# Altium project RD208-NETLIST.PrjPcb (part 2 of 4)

## Sheet 4.SchDoc
size 420 x 297 mm
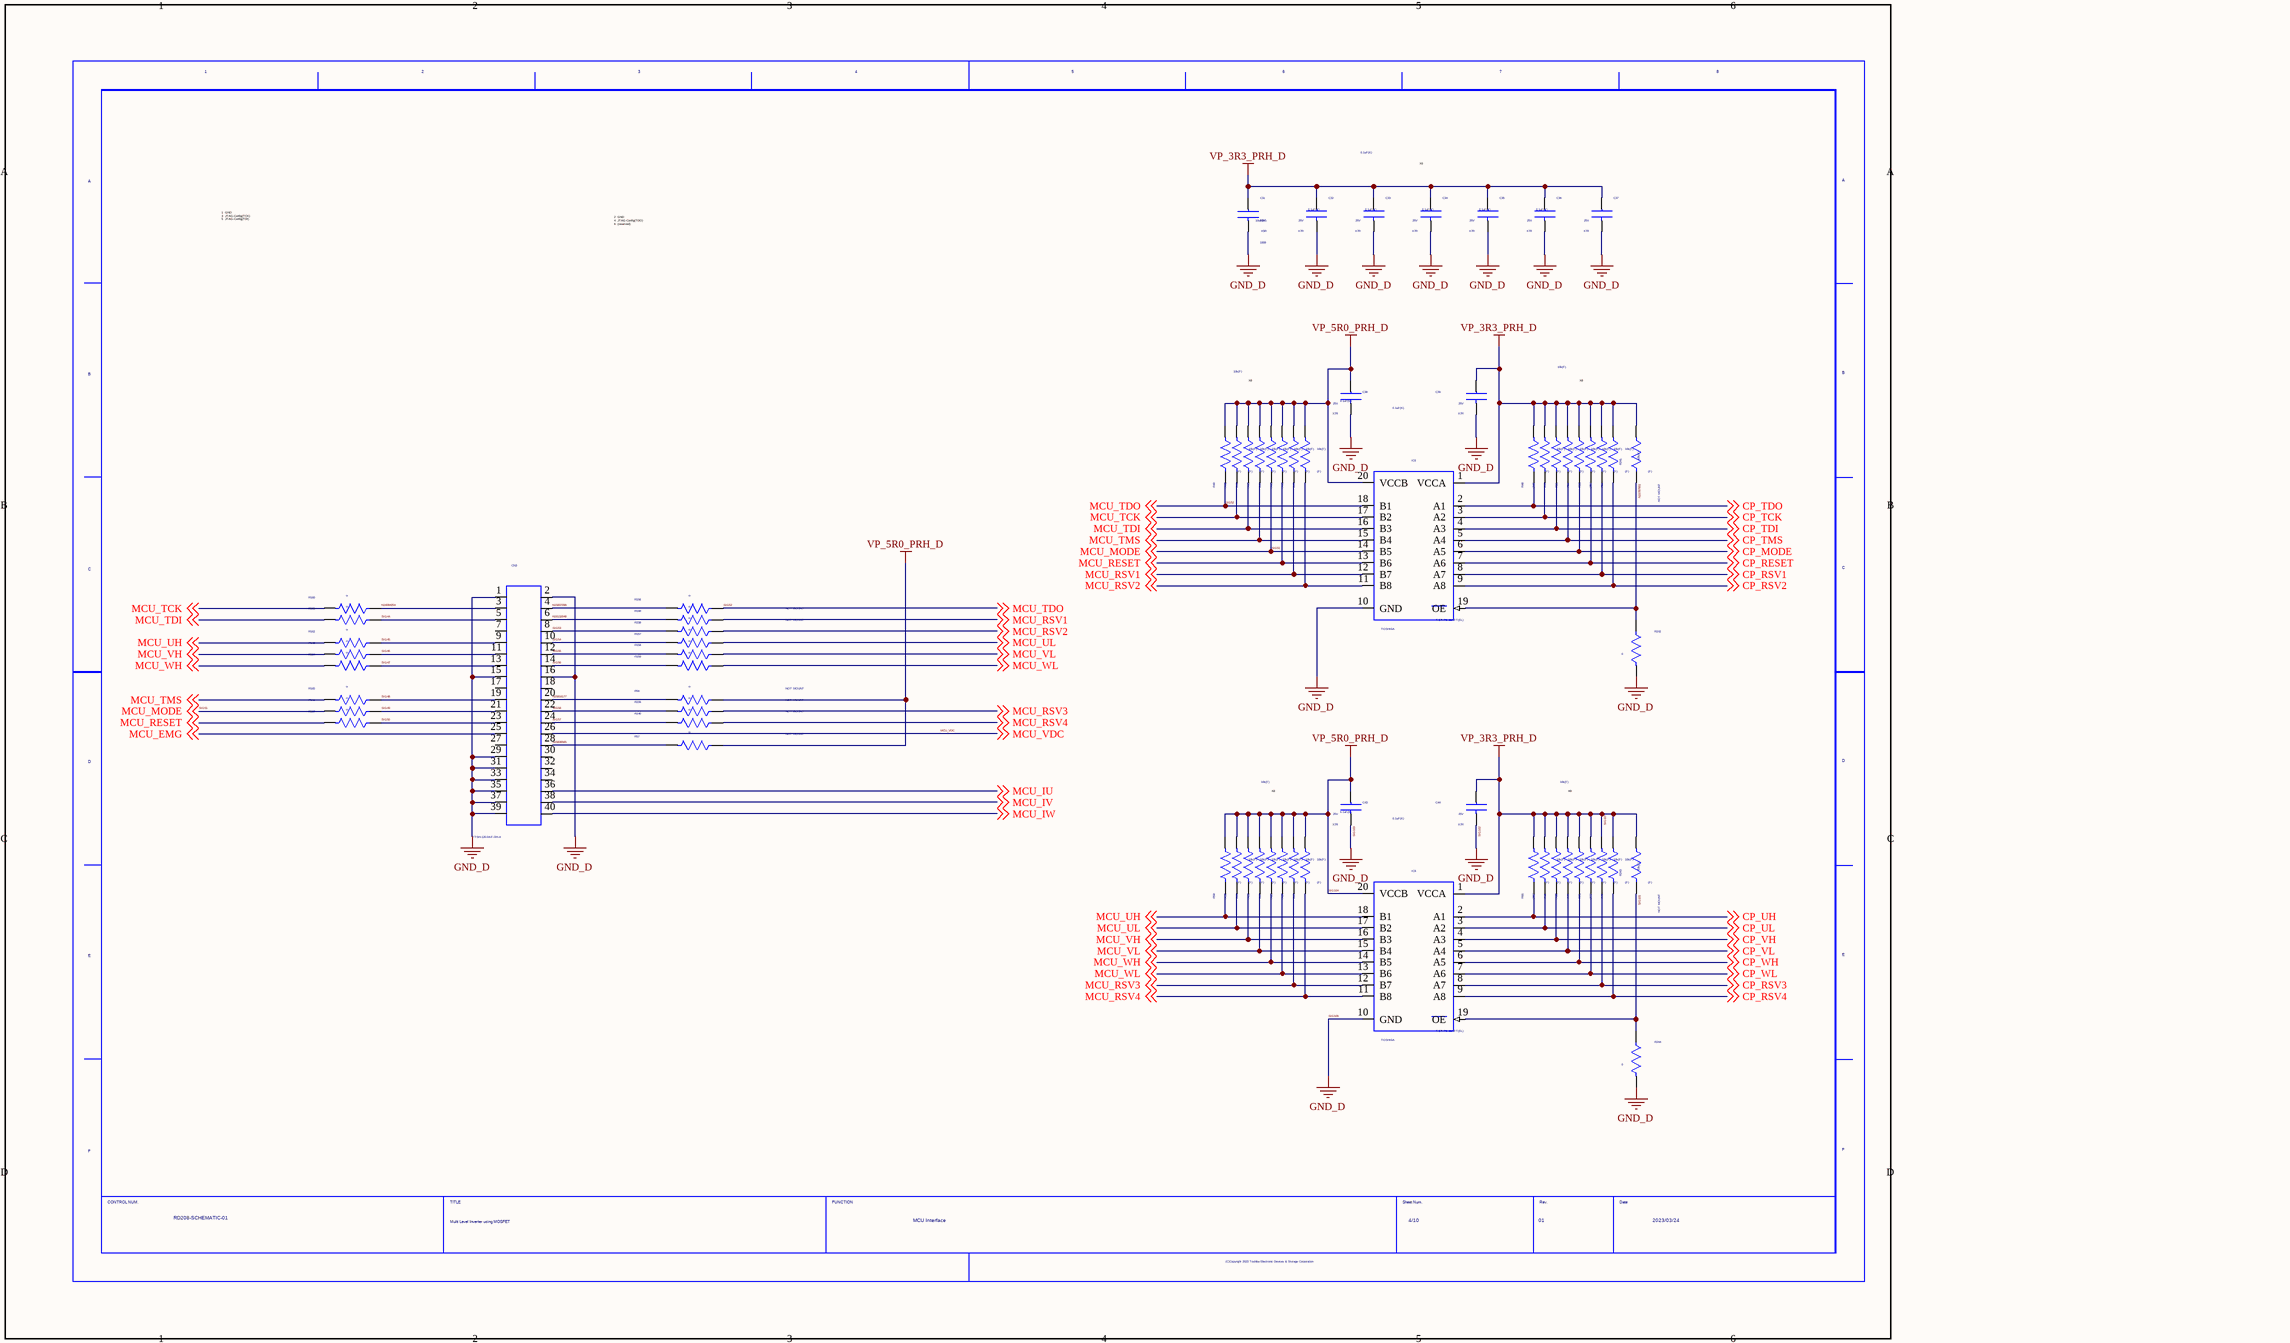
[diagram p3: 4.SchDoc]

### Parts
(Parts that share a designator on the sheet are numbered #1, #2 ... from top to bottom, then left to right.)
C31  VAL2: 10V  SIZECODESMD: 1608  VALUE4: X5R  VAL1: 10uF(M)  (hidden comment: GRM188R61A106ME69D)
C32  VAL2: 25V  VALUE4: X7R  VAL1: 0.1uF(K)  (hidden comment: GRM155R71E104KE14D)
C33  VAL2: 25V  VALUE4: X7R  VAL1: 0.1uF(K)  (hidden comment: GRM155R71E104KE14D)
C34  VAL2: 25V  VALUE4: X7R  VAL1: 0.1uF(K)  (hidden comment: GRM155R71E104KE14D)
C35  VAL2: 25V  VALUE4: X7R  VAL1: 0.1uF(K)  (hidden comment: GRM155R71E104KE14D)
C36  VAL2: 25V  VALUE4: X7R  VAL1: 0.1uF(K)  (hidden comment: GRM155R71E104KE14D)
C37  VAL2: 25V  VALUE4: X7R  VAL1: 0.1uF(K)  (hidden comment: GRM155R71E104KE14D)
C38  VAL2: 25V  VALUE4: X7R  VAL1: 0.1uF(K)  (hidden comment: GRM155R71E104KE14D)
C39  VAL2: 25V  VALUE4: X7R  VAL1: 0.1uF(K)  (hidden comment: GRM155R71E104KE14D)
C43  VAL2: 25V  VALUE4: X7R  VAL1: 0.1uF(K)  (hidden comment: GRM155R71E104KE14D)
C44  VAL2: 25V  VALUE4: X7R  VAL1: 0.1uF(K)  (hidden comment: GRM155R71E104KE14D)
CN3  VAL1: FTSH-120-04-F-DH-A  (hidden comment: FTSH_120_04_F_DH_A)
IC6  VAL1: TC7MPB9307FT(EL)  USERCOMPTEXT3: TOSHIBA  (hidden comment: TC7MPB9307FT)
IC8  VAL1: TC7MPB9307FT(EL)  USERCOMPTEXT3: TOSHIBA  (hidden comment: TC7MPB9307FT)
R40  VALUE4: (F)  VAL1: 10k(F)  (hidden comment: ERJ2RKF1002X)
R41  VALUE4: (F)  VAL1: 10k(F)  (hidden comment: ERJ2RKF1002X)
R42  VALUE4: (F)  VAL1: 10k(F)  (hidden comment: ERJ2RKF1002X)
R43  VALUE4: (F)  VAL1: 10k(F)  (hidden comment: ERJ2RKF1002X)
R44  VALUE4: (F)  VAL1: 10k(F)  (hidden comment: ERJ2RKF1002X)
R45  VALUE4: (F)  VAL1: 10k(F)  (hidden comment: ERJ2RKF1002X)
R46  VALUE4: (F)  VAL1: 10k(F)  (hidden comment: ERJ2RKF1002X)
R47  VALUE4: (F)  VAL1: 10k(F)  (hidden comment: ERJ2RKF1002X)
R48  VALUE4: (F)  VAL1: 10k(F)  (hidden comment: ERJ2RKF1002X)
R49  VALUE4: (F)  VAL1: 10k(F)  (hidden comment: ERJ2RKF1002X)
R50  VALUE4: (F)  VAL1: 10k(F)  (hidden comment: ERJ2RKF1002X)
R51  VALUE4: (F)  VAL1: 10k(F)  (hidden comment: ERJ2RKF1002X)
R52  VALUE4: (F)  VAL1: 10k(F)  (hidden comment: ERJ2RKF1002X)
R53  VALUE4: (F)  VAL1: 10k(F)  (hidden comment: ERJ2RKF1002X)
R54  VALUE4: (F)  VAL1: 10k(F)  (hidden comment: ERJ2RKF1002X)
R55  VALUE4: (F)  VAL1: 10k(F)  (hidden comment: ERJ2RKF1002X)
R56  VAL1: 0  NOTMOUNT: NOT MOUNT  (hidden comment: ERJ2GE0R00X)
R57  VAL1: 0  NOTMOUNT: NOT MOUNT  (hidden comment: ERJ2GE0R00X)
R58  VALUE4: (F)  VAL1: 10k(F)  (hidden comment: ERJ2RKF1002X)
R59  VALUE4: (F)  VAL1: 10k(F)  (hidden comment: ERJ2RKF1002X)
R60  VALUE4: (F)  VAL1: 10k(F)  (hidden comment: ERJ2RKF1002X)
R61  VALUE4: (F)  VAL1: 10k(F)  (hidden comment: ERJ2RKF1002X)
R62  VALUE4: (F)  VAL1: 10k(F)  (hidden comment: ERJ2RKF1002X)
R63  VALUE4: (F)  VAL1: 10k(F)  (hidden comment: ERJ2RKF1002X)
R64  VALUE4: (F)  VAL1: 10k(F)  (hidden comment: ERJ2RKF1002X)
R65  VALUE4: (F)  VAL1: 10k(F)  (hidden comment: ERJ2RKF1002X)
R66  VALUE4: (F)  VAL1: 10k(F)  (hidden comment: ERJ2RKF1002X)
R67  VALUE4: (F)  VAL1: 10k(F)  (hidden comment: ERJ2RKF1002X)
R68  VALUE4: (F)  VAL1: 10k(F)  (hidden comment: ERJ2RKF1002X)
R69  VALUE4: (F)  VAL1: 10k(F)  (hidden comment: ERJ2RKF1002X)
R70  VALUE4: (F)  VAL1: 10k(F)  (hidden comment: ERJ2RKF1002X)
R71  VALUE4: (F)  VAL1: 10k(F)  (hidden comment: ERJ2RKF1002X)
R72  VALUE4: (F)  VAL1: 10k(F)  (hidden comment: ERJ2RKF1002X)
R73  VALUE4: (F)  VAL1: 10k(F)  (hidden comment: ERJ2RKF1002X)
R156  VAL1: 0  (hidden comment: ERJ2GE0R00X)
R157  VAL1: 0  (hidden comment: ERJ2GE0R00X)
R158  VAL1: 0  (hidden comment: ERJ2GE0R00X)
R159  VAL1: 0  (hidden comment: ERJ2GE0R00X)
R160  VAL1: 0  (hidden comment: ERJ2GE0R00X)
R161  VAL1: 0  (hidden comment: ERJ2GE0R00X)
R162  VAL1: 0  (hidden comment: ERJ2GE0R00X)
R163  VAL1: 0  (hidden comment: ERJ2GE0R00X)
R164  VAL1: 0  (hidden comment: ERJ2GE0R00X)
R165  VAL1: 0  (hidden comment: ERJ2GE0R00X)
R166  VAL1: 0  (hidden comment: ERJ2GE0R00X)
R167  VAL1: 0  (hidden comment: ERJ2GE0R00X)
R198  VAL1: 0  NOTMOUNT: NOT MOUNT  (hidden comment: ERJ2GE0R00X)
R238  VAL1: 0  NOTMOUNT: NOT MOUNT  (hidden comment: ERJ2GE0R00X)
R239  VAL1: 0  NOTMOUNT: NOT MOUNT  (hidden comment: ERJ2GE0R00X)
R240  VAL1: 0  NOTMOUNT: NOT MOUNT  (hidden comment: ERJ2GE0R00X)
R241  VALUE4: (F)  VAL1: 10k(F)  NOTMOUNT: NOT MOUNT  (hidden comment: ERJ2RKF1002X)
R242  VAL1: 0  (hidden comment: ERJ2GE0R00X)
R243  VALUE4: (F)  VAL1: 10k(F)  NOTMOUNT: NOT MOUNT  (hidden comment: ERJ2RKF1002X)
R244  VAL1: 0  (hidden comment: ERJ2GE0R00X)
U?#4  DATE: 2023/03/24  TITLE: Multi Level Inverter using MOSFET  REVISION: 01  SHEETNUMBER: 4/10  DRAWINGNUMBER: RD208-SCHEMATIC-01  FUNCTION: MCU Interface  (hidden comment: WAKU_DEF100)

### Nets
GND_D: C31.2 C32.2 C33.2 C34.2 C35.2 C36.2 C37.2 C38.2 C39.2 C43.2 C44.2 CN3.1 CN3.2 CN3.15 CN3.16 CN3.29 CN3.31 CN3.33 CN3.35 CN3.37 CN3.39 IC6.10(GND) IC8.10(GND) R242.1 R244.1  [also labelled SIG102, SIG103, SIG106]  [project net SIG10]
SIG104: C38.1 C43.1 IC6.20(VCCB) IC8.20(VCCB) R40.1 R41.1 R42.1 R43.1 R44.1 R45.1 R46.1 R47.1 R56.2 R57.2 R58.1 R59.1 R60.1 R61.1 R62.1 R63.1 R64.1 R65.1  [also labelled VP_5R0_PRH_D]
SIG107: C31.1 C32.1 C33.1 C34.1 C35.1 C36.1 C37.1 C39.1 C44.1 IC6.1(VCCA) IC8.1(VCCA) R48.1 R49.1 R50.1 R51.1 R52.1 R53.1 R54.1 R55.1 R66.1 R67.1 R68.1 R69.1 R70.1 R71.1 R72.1 R73.1 R241.1 R243.1  [also labelled VP_3R3_PRH_D]
CP_MODE: IC6.6(A5) R52.2 ; off-sheet CP_MODE
CP_RESET: IC6.7(A6) R53.2 ; off-sheet CP_RESET
CP_RSV1: IC6.8(A7) R54.2 ; off-sheet CP_RSV1
CP_RSV2: IC6.9(A8) R55.2 ; off-sheet CP_RSV2
CP_RSV3: IC8.8(A7) R72.2 ; off-sheet CP_RSV3
CP_RSV4: IC8.9(A8) R73.2 ; off-sheet CP_RSV4
CP_TCK: IC6.3(A2) R49.2 ; off-sheet CP_TCK
CP_TDI: IC6.4(A3) R50.2 ; off-sheet CP_TDI
CP_TDO: IC6.2(A1) R48.2 ; off-sheet CP_TDO
CP_TMS: IC6.5(A4) R51.2 ; off-sheet CP_TMS
CP_UH: IC8.2(A1) R66.2 ; off-sheet CP_UH
CP_UL: IC8.3(A2) R67.2 ; off-sheet CP_UL
CP_VH: IC8.4(A3) R68.2 ; off-sheet CP_VH
CP_VL: IC8.5(A4) R69.2 ; off-sheet CP_VL
CP_WH: IC8.6(A5) R70.2 ; off-sheet CP_WH
CP_WL: IC8.7(A6) R71.2 ; off-sheet CP_WL
MCU_EMG: CN3.25 ; off-sheet MCU_EMG
MCU_IU: CN3.36 ; off-sheet MCU_IU
MCU_IV: CN3.38 ; off-sheet MCU_IV
MCU_IW: CN3.40 ; off-sheet MCU_IW
MCU_RESET: IC6.13(B6) R45.2 R167.1 ; off-sheet MCU_RESET
MCU_RSV1: IC6.12(B7) R46.2 R198.2 ; off-sheet MCU_RSV1
MCU_RSV2: IC6.11(B8) R47.2 R238.2 ; off-sheet MCU_RSV2
MCU_RSV3: IC8.12(B7) R64.2 R239.2 ; off-sheet MCU_RSV3
MCU_RSV4: IC8.11(B8) R65.2 R240.2 ; off-sheet MCU_RSV4
MCU_TCK: IC6.17(B2) R41.2 R160.1 ; off-sheet MCU_TCK
MCU_TDI: IC6.16(B3) R42.2 R161.1 ; off-sheet MCU_TDI
MCU_TMS: IC6.15(B4) R43.2 R165.1 ; off-sheet MCU_TMS
MCU_UH: IC8.18(B1) R58.2 R162.1 ; off-sheet MCU_UH
MCU_UL: IC8.17(B2) R59.2 R157.2 ; off-sheet MCU_UL
MCU_VDC: CN3.26 ; off-sheet MCU_VDC
MCU_VH: IC8.16(B3) R60.2 R163.1 ; off-sheet MCU_VH
MCU_VL: IC8.15(B4) R61.2 R158.2 ; off-sheet MCU_VL
MCU_WH: IC8.14(B5) R62.2 R164.1 ; off-sheet MCU_WH
MCU_WL: IC8.13(B6) R63.2 R159.2 ; off-sheet MCU_WL
N15787951: IC6.19(OE) R241.2 R242.2
N15816177: CN3.20 R56.1
N15836565: CN3.28 R57.1
N15837096: CN3.4 R156.1
N16084254: CN3.3 R160.2
N16132048: CN3.6 R198.1
SIG44: CN3.5 R161.2
SIG45: CN3.9 R162.2
SIG46: CN3.11 R163.2
SIG47: CN3.13 R164.2
SIG48: CN3.19 R165.2
SIG49: CN3.21 R166.2
SIG50: CN3.23 R167.2
SIG51: IC6.14(B5) R44.2 R166.1 ; off-sheet MCU_MODE  [also labelled MCU_MODE]
SIG52: IC6.18(B1) R40.2 R156.2 ; off-sheet MCU_TDO  [also labelled MCU_TDO]
SIG53: CN3.8 R238.1
SIG54: CN3.10 R157.1
SIG55: CN3.12 R158.1
SIG56: CN3.14 R159.1
SIG57: CN3.24 R240.1
SIG58: CN3.22 R239.1
SIG101: IC8.19(OE) R243.2 R244.2

Not connected (* = marked no-connect by the designer): CN3 7 17 18 27 30 32 34

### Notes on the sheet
- X6
- 1  GND
  3  JTAG-Config(TCK)
  5  JTAG-Config(TDI)
  7  (n.c.)
  9  High-side gate driver signal (U-Phase)
  11  High-side gate driver signal (V-Phase)
  13  High-side gate driver signal (W-Phase)
  15  GND
  17  (n.c.)
  19  JTAG-Config(TMS)
  21  CPLD-MODE
  23  CPLD-RESET
  25  EMG
  27  (n.c.)
  29  GND
  31  GND
  33  GND
  35  GND
  37  GND
  39  GND
- 2  GND
  4  JTAG-Config(TDO)
  6  (reserved)
  8  (reserved)
  10  Low-side gate driver signal (U-Phase)
  12  Low-side gate driver signal (V-Phase)
  14  Low-side gate driver signal (W-Phase)
  16  GND
  18  (n.c.)
  20  5V Input
  22  (reserved)
  24  (reserved)
  26  Inverter bus voltage divider voltage (Vdc)
  28  5V Input
  30  (n.c.)
  32  (n.c.)
  34  (n.c.)
  36  U-phase current value
  38  V-phase current value
  40  W-phase current value
- X8

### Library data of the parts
C31 = GRM188R61A106ME69D: MANUFACTURER: MURATA; ITEM: CAP Ceramic; TIME: 08:44:46; UPDATEUSER: t5459927; SAVECOUNT: 1; OriginalSymbolOrigin: (0,0); INSTANCENAME: INS15850047
C32 = GRM155R71E104KE14D: MANUFACTURER: MURATA; ITEM: CAP Ceramic; SIZECODESMD: 1005; TIME: 08:44:45; UPDATEUSER: t5459927; SAVECOUNT: 1; OriginalSymbolOrigin: (0,0); INSTANCENAME: INS15848437
C33 = GRM155R71E104KE14D: MANUFACTURER: MURATA; ITEM: CAP Ceramic; SIZECODESMD: 1005; TIME: 08:44:45; UPDATEUSER: t5459927; SAVECOUNT: 1; OriginalSymbolOrigin: (0,0); INSTANCENAME: INS15848594
C34 = GRM155R71E104KE14D: MANUFACTURER: MURATA; ITEM: CAP Ceramic; SIZECODESMD: 1005; TIME: 08:44:45; UPDATEUSER: t5459927; SAVECOUNT: 1; OriginalSymbolOrigin: (0,0); INSTANCENAME: INS15848750
C35 = GRM155R71E104KE14D: MANUFACTURER: MURATA; ITEM: CAP Ceramic; SIZECODESMD: 1005; TIME: 08:44:45; UPDATEUSER: t5459927; SAVECOUNT: 1; OriginalSymbolOrigin: (0,0); INSTANCENAME: INS15848907
C36 = GRM155R71E104KE14D: MANUFACTURER: MURATA; ITEM: CAP Ceramic; SIZECODESMD: 1005; TIME: 08:44:45; UPDATEUSER: t5459927; SAVECOUNT: 1; OriginalSymbolOrigin: (0,0); INSTANCENAME: INS15849085
C37 = GRM155R71E104KE14D: MANUFACTURER: MURATA; ITEM: CAP Ceramic; SIZECODESMD: 1005; TIME: 08:44:45; UPDATEUSER: t5459927; SAVECOUNT: 1; OriginalSymbolOrigin: (0,0); INSTANCENAME: INS15849105
C38 C43 = GRM155R71E104KE14D: MANUFACTURER: MURATA; ITEM: CAP Ceramic; SIZECODESMD: 1005; TIME: 08:44:45; UPDATEUSER: t5459927; SAVECOUNT: 1; OriginalSymbolOrigin: (0,0); INSTANCENAME: INS15846963
C39 C44 = GRM155R71E104KE14D: MANUFACTURER: MURATA; ITEM: CAP Ceramic; SIZECODESMD: 1005; TIME: 08:44:45; UPDATEUSER: t5459927; SAVECOUNT: 1; OriginalSymbolOrigin: (0,0); INSTANCENAME: INS15846983
CN3 = FTSH_120_04_F_DH_A: MANUFACTURER: Samtec; COMP: FTSH-120-04-F-DH-A-AEP; ITEM: Connector; TIME: 08:44:46; UPDATEUSER: t5459927; SAVECOUNT: 1; SAVEAREA0: -36272,-54408,42126,2984; OriginalSymbolOrigin: (0,0); INSTANCENAME: INS16810272
IC6 IC8 = TC7MPB9307FT: ITEM: IC BUS SW; VAL2: BUS SW; TIME: 08:44:46; UPDATEUSER: PS4_common_PC; UPDATETIME: 15:59:21; SAVECOUNT: 4; SAVEAREA0: -17429,-46731,34553,-8676; OriginalSymbolOrigin: (0,0)
R40 R58 = ERJ2RKF1002X: MANUFACTURER: Panasonic; ITEM: Register; VAL2: 100mW; SIZECODESMD: 1005; TIME: 08:44:45; UPDATEUSER: t5459927; SAVECOUNT: 1; OriginalSymbolOrigin: (0,0); INSTANCENAME: INS15795606
R41 R59 = ERJ2RKF1002X: MANUFACTURER: Panasonic; ITEM: Register; VAL2: 100mW; SIZECODESMD: 1005; TIME: 08:44:45; UPDATEUSER: t5459927; SAVECOUNT: 1; OriginalSymbolOrigin: (0,0); INSTANCENAME: INS17125057
R42 R60 = ERJ2RKF1002X: MANUFACTURER: Panasonic; ITEM: Register; VAL2: 100mW; SIZECODESMD: 1005; TIME: 08:44:45; UPDATEUSER: t5459927; SAVECOUNT: 1; OriginalSymbolOrigin: (0,0); INSTANCENAME: INS17125150
R43 R61 = ERJ2RKF1002X: MANUFACTURER: Panasonic; ITEM: Register; VAL2: 100mW; SIZECODESMD: 1005; TIME: 08:44:45; UPDATEUSER: t5459927; SAVECOUNT: 1; OriginalSymbolOrigin: (0,0); INSTANCENAME: INS17125244
R44 R62 = ERJ2RKF1002X: MANUFACTURER: Panasonic; ITEM: Register; VAL2: 100mW; SIZECODESMD: 1005; TIME: 08:44:45; UPDATEUSER: t5459927; SAVECOUNT: 1; OriginalSymbolOrigin: (0,0); INSTANCENAME: INS17125339
R45 R63 = ERJ2RKF1002X: MANUFACTURER: Panasonic; ITEM: Register; VAL2: 100mW; SIZECODESMD: 1005; TIME: 08:44:45; UPDATEUSER: t5459927; SAVECOUNT: 1; OriginalSymbolOrigin: (0,0); INSTANCENAME: INS17125433
R46 R64 = ERJ2RKF1002X: MANUFACTURER: Panasonic; ITEM: Register; VAL2: 100mW; SIZECODESMD: 1005; TIME: 08:44:45; UPDATEUSER: t5459927; SAVECOUNT: 1; OriginalSymbolOrigin: (0,0); INSTANCENAME: INS17125527
R47 R65 = ERJ2RKF1002X: MANUFACTURER: Panasonic; ITEM: Register; VAL2: 100mW; SIZECODESMD: 1005; TIME: 08:44:45; UPDATEUSER: t5459927; SAVECOUNT: 1; OriginalSymbolOrigin: (0,0); INSTANCENAME: INS17125624
R48 R66 = ERJ2RKF1002X: MANUFACTURER: Panasonic; ITEM: Register; VAL2: 100mW; SIZECODESMD: 1005; TIME: 08:44:45; UPDATEUSER: t5459927; SAVECOUNT: 1; OriginalSymbolOrigin: (0,0); INSTANCENAME: INS17126711
R49 R67 = ERJ2RKF1002X: MANUFACTURER: Panasonic; ITEM: Register; VAL2: 100mW; SIZECODESMD: 1005; TIME: 08:44:45; UPDATEUSER: t5459927; SAVECOUNT: 1; OriginalSymbolOrigin: (0,0); INSTANCENAME: INS17126722
R50 R68 = ERJ2RKF1002X: MANUFACTURER: Panasonic; ITEM: Register; VAL2: 100mW; SIZECODESMD: 1005; TIME: 08:44:45; UPDATEUSER: t5459927; SAVECOUNT: 1; OriginalSymbolOrigin: (0,0); INSTANCENAME: INS17126733
R51 R69 = ERJ2RKF1002X: MANUFACTURER: Panasonic; ITEM: Register; VAL2: 100mW; SIZECODESMD: 1005; TIME: 08:44:45; UPDATEUSER: t5459927; SAVECOUNT: 1; OriginalSymbolOrigin: (0,0); INSTANCENAME: INS17126744
R52 R70 = ERJ2RKF1002X: MANUFACTURER: Panasonic; ITEM: Register; VAL2: 100mW; SIZECODESMD: 1005; TIME: 08:44:45; UPDATEUSER: t5459927; SAVECOUNT: 1; OriginalSymbolOrigin: (0,0); INSTANCENAME: INS17126755
R53 R71 = ERJ2RKF1002X: MANUFACTURER: Panasonic; ITEM: Register; VAL2: 100mW; SIZECODESMD: 1005; TIME: 08:44:45; UPDATEUSER: t5459927; SAVECOUNT: 1; OriginalSymbolOrigin: (0,0); INSTANCENAME: INS17126766
R54 R72 = ERJ2RKF1002X: MANUFACTURER: Panasonic; ITEM: Register; VAL2: 100mW; SIZECODESMD: 1005; TIME: 08:44:45; UPDATEUSER: t5459927; SAVECOUNT: 1; OriginalSymbolOrigin: (0,0); INSTANCENAME: INS17126777
R55 R73 = ERJ2RKF1002X: MANUFACTURER: Panasonic; ITEM: Register; VAL2: 100mW; SIZECODESMD: 1005; TIME: 08:44:45; UPDATEUSER: t5459927; SAVECOUNT: 1; OriginalSymbolOrigin: (0,0); INSTANCENAME: INS17126788
R56 R57 = ERJ2GE0R00X: MANUFACTURER: Panasonic; ITEM: Register; VAL2: 1/10W; SIZECODESMD: 1005; TIME: 08:44:45; UPDATEUSER: t5459927; SAVECOUNT: 1; OriginalSymbolOrigin: (0,0); INSTANCENAME: INS17265222
R156-R159 = ERJ2GE0R00X: MANUFACTURER: Panasonic; ITEM: Register; VAL2: 1/10W; SIZECODESMD: 1005; TIME: 08:44:45; UPDATEUSER: t5459927; SAVECOUNT: 1; OriginalSymbolOrigin: (0,0); INSTANCENAME: INS16082588
R160-R167 = ERJ2GE0R00X: MANUFACTURER: Panasonic; ITEM: Register; VAL2: 1/10W; SIZECODESMD: 1005; TIME: 08:44:45; UPDATEUSER: t5459927; SAVECOUNT: 1; OriginalSymbolOrigin: (0,0); INSTANCENAME: INS16084230
R198 R238-R240 = ERJ2GE0R00X: MANUFACTURER: Panasonic; ITEM: Register; VAL2: 1/10W; SIZECODESMD: 1005; TIME: 08:44:45; UPDATEUSER: t5459927; SAVECOUNT: 1; OriginalSymbolOrigin: (0,0); INSTANCENAME: INS16693080
R241 R243 = ERJ2RKF1002X: MANUFACTURER: Panasonic; ITEM: Register; VAL2: 100mW; SIZECODESMD: 1005; TIME: 08:44:45; UPDATEUSER: t5459927; SAVECOUNT: 1; OriginalSymbolOrigin: (0,0); INSTANCENAME: INS16663974
R242 R244 = ERJ2GE0R00X: MANUFACTURER: Panasonic; ITEM: Register; VAL2: 1/10W; SIZECODESMD: 1005; TIME: 08:44:45; UPDATEUSER: t5459927; SAVECOUNT: 1; OriginalSymbolOrigin: (0,0); INSTANCENAME: INS16664582
U?#4 = WAKU_DEF100: PLOTTIME: HH:MM; SAVEAREA0: 185750,-43960,448537,75779; TIME: 14:30:25; UPDATEUSER: PS4_common_PC; UPDATETIME: 08:24:35; SAVECOUNT: 8; OriginalSymbolOrigin: (10160,284480)

## Sheet 5.SchDoc
size 420 x 297 mm
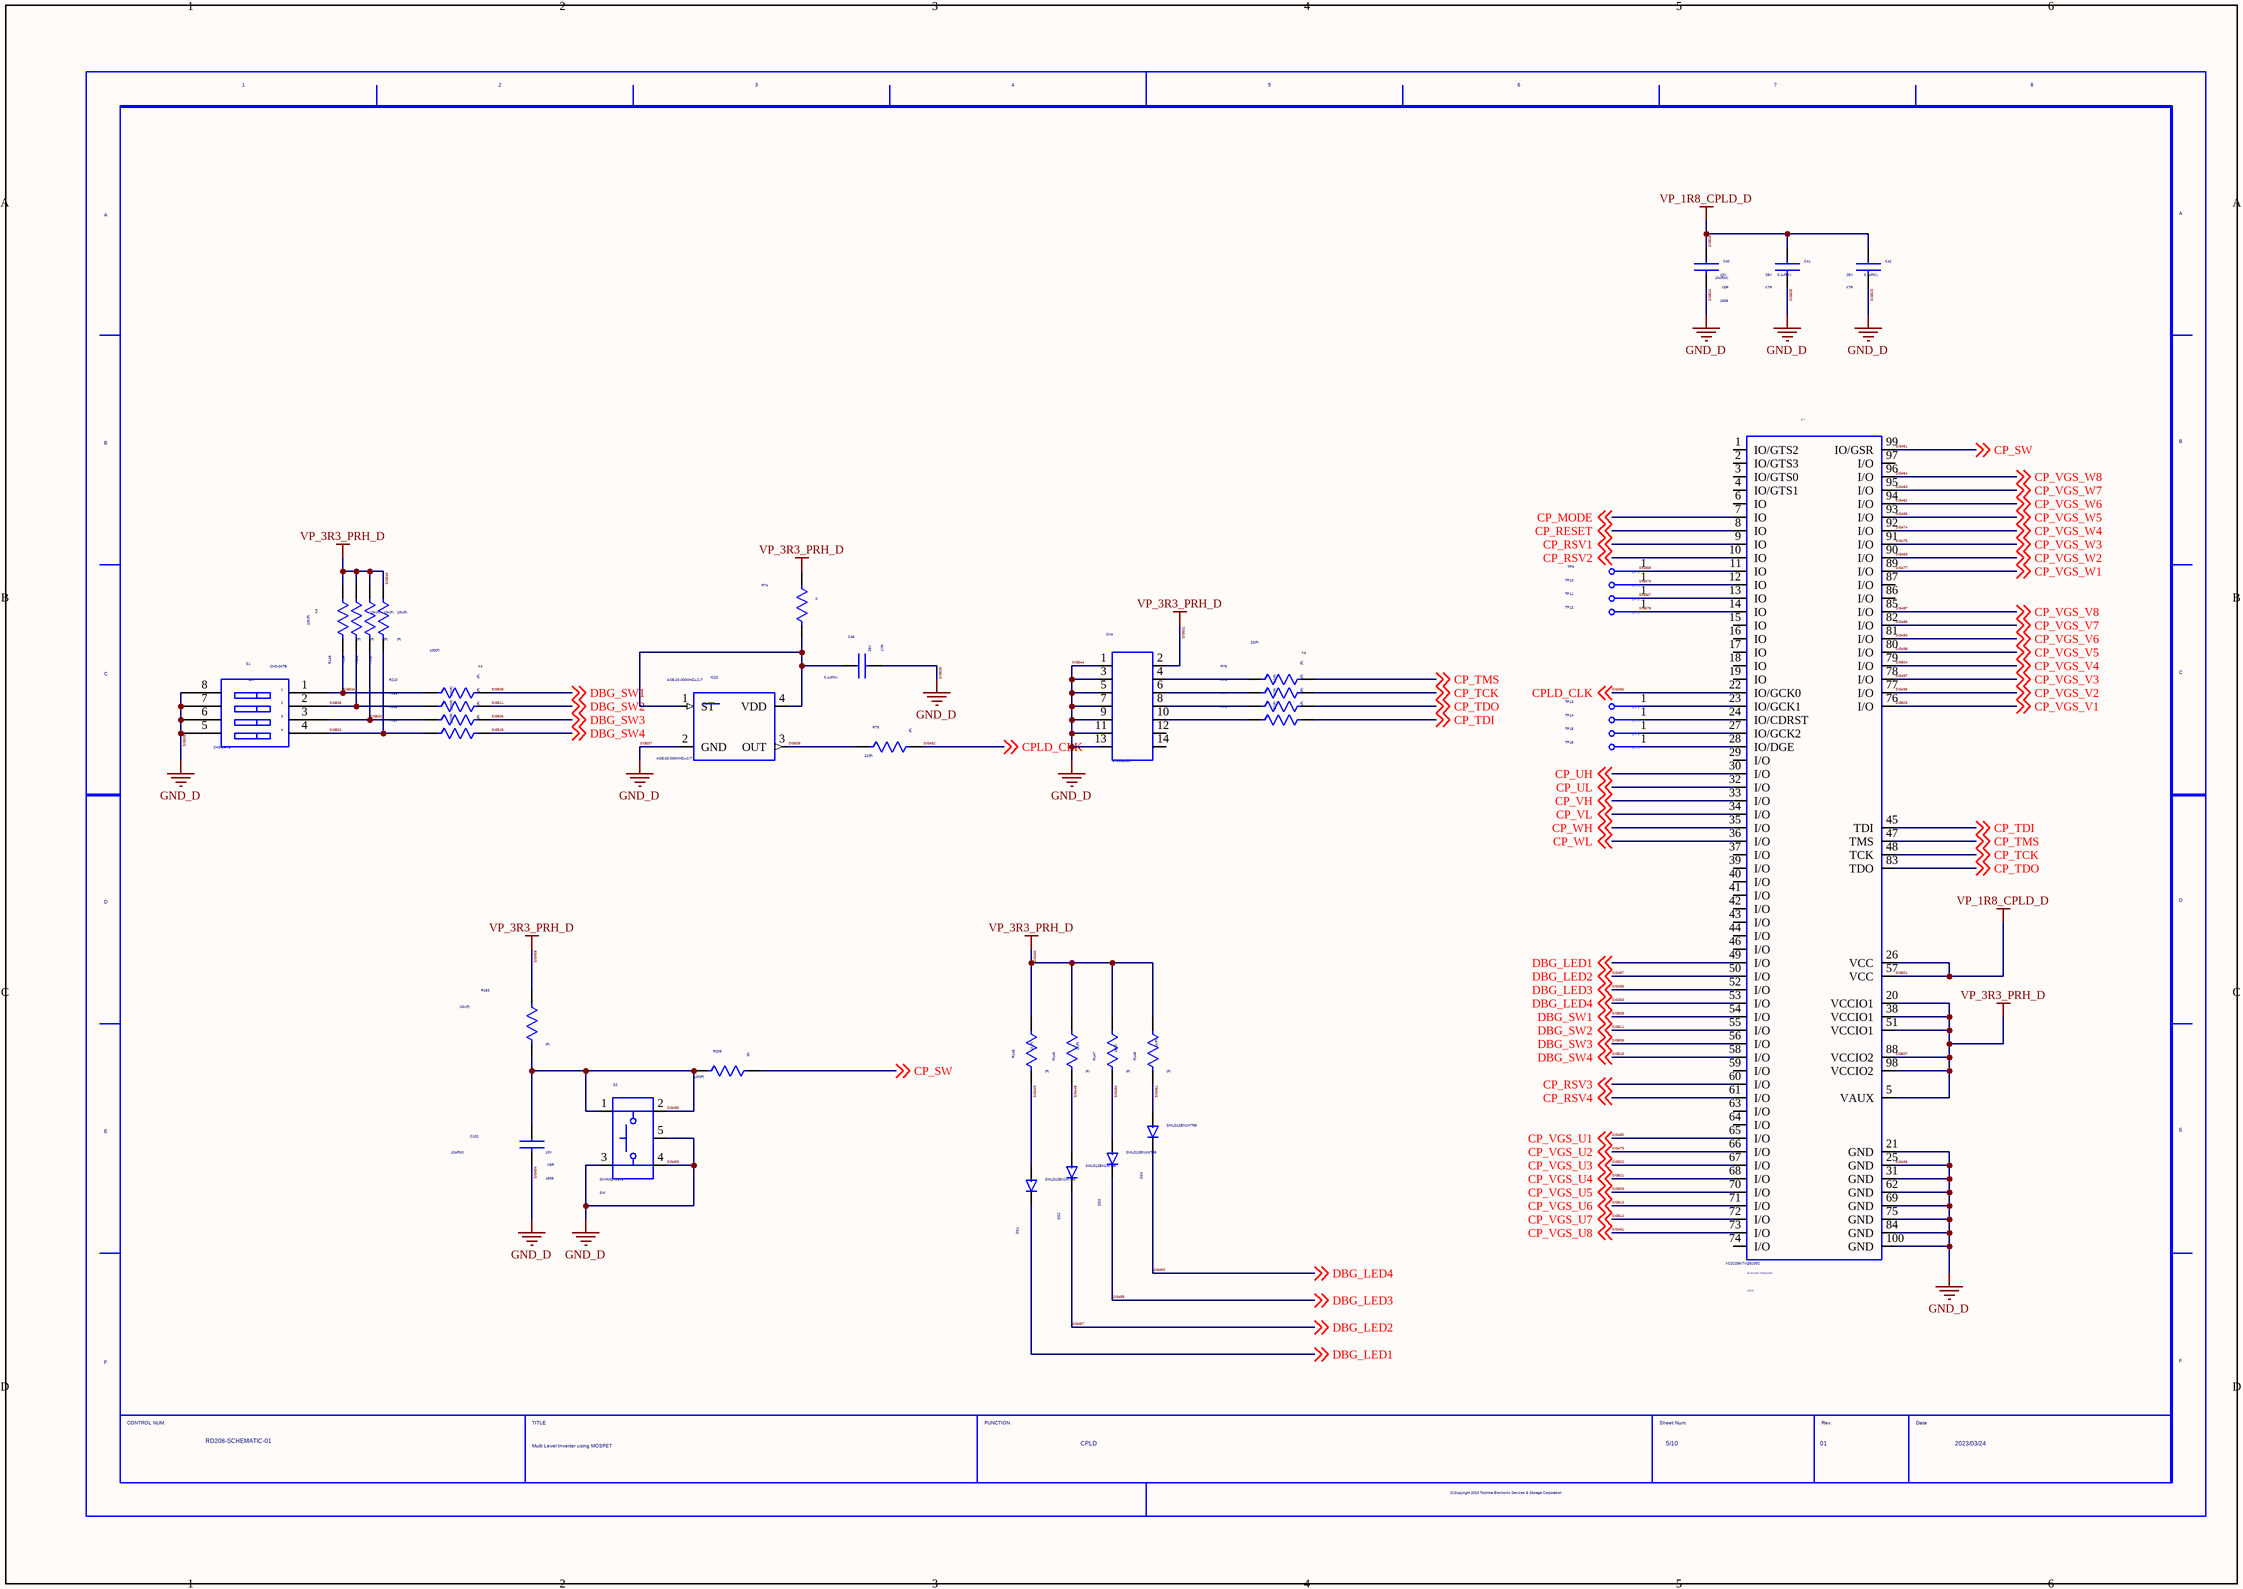
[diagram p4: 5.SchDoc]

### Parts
(Parts that share a designator on the sheet are numbered #1, #2 ... from top to bottom, then left to right.)
C40  VAL2: 10V  SIZECODESMD: 1608  VALUE4: X5R  VAL1: 10uF(M)  (hidden comment: GRM188R61A106ME69D)
C41  VAL2: 25V  VALUE4: X7R  VAL1: 0.1uF(K)  (hidden comment: GRM155R71E104KE14D)
C42  VAL2: 25V  VALUE4: X7R  VAL1: 0.1uF(K)  (hidden comment: GRM155R71E104KE14D)
C46  VAL2: 25V  VALUE4: X7R  VAL1: 0.1uF(K)  (hidden comment: GRM155R71E104KE14D)
C102  VAL2: 10V  SIZECODESMD: 1608  VALUE4: X5R  VAL1: 10uF(M)  (hidden comment: GRM188R61A106ME69D)
CN4  VAL1: 878311420  (hidden comment: 0878311420)
DS1  SMLD12EN1WT86
DS2  SMLD12EN1WT86
DS3  SMLD12EN1WT86
DS4  SMLD12EN1WT86
IC7  VAL2: CPLD  VAL1: XC2C256-7VQG100C  (hidden comment: XC2C256_7VQG100C)
IC22  VAL1: ASE-20.000MHZ-LC-T  (hidden comment: ASE_20_000MHZ_LC_T)
R74  VAL1: 0  (hidden comment: ERJ2GE0R00X)
R75  VALUE4: (F)  VAL1: 22(F)  (hidden comment: ERJ2RKF22R0X)
R76  VALUE4: (F)  VAL1: 22(F)  (hidden comment: ERJ2RKF22R0X)
R77  VALUE4: (F)  VAL1: 22(F)  (hidden comment: ERJ2RKF22R0X)
R78  VALUE4: (F)  VAL1: 22(F)  (hidden comment: ERJ2RKF22R0X)
R79  VALUE4: (F)  VAL1: 22(F)  (hidden comment: ERJ2RKF22R0X)
R145  VALUE4: (F)  VAL1: 1k(F)  (hidden comment: ERJ2RKF1001X)
R146  VALUE4: (F)  VAL1: 1k(F)  (hidden comment: ERJ2RKF1001X)
R147  VALUE4: (F)  VAL1: 1k(F)  (hidden comment: ERJ2RKF1001X)
R148  VALUE4: (F)  VAL1: 1k(F)  (hidden comment: ERJ2RKF1001X)
R149  VALUE4: (F)  VAL1: 10k(F)  (hidden comment: ERJ2RKF1002X)
R150  VALUE4: (F)  VAL1: 10k(F)  (hidden comment: ERJ2RKF1002X)
R151  VALUE4: (F)  VAL1: 10k(F)  (hidden comment: ERJ2RKF1002X)
R152  VALUE4: (F)  VAL1: 10k(F)  (hidden comment: ERJ2RKF1002X)
R153  VALUE4: (F)  VAL1: 10k(F)  (hidden comment: ERJ2RKF1002X)
R209  VALUE4: (F)  VAL1: 100(F)  (hidden comment: ERJ2RKF1000X)
R210  VALUE4: (F)  VAL1: 100(F)  (hidden comment: ERJ2RKF1000X)
R211  VALUE4: (F)  VAL1: 100(F)  (hidden comment: ERJ2RKF1000X)
R212  VALUE4: (F)  VAL1: 100(F)  (hidden comment: ERJ2RKF1000X)
R213  VALUE4: (F)  VAL1: 100(F)  (hidden comment: ERJ2RKF1000X)
S1  SCH_NAME: CHS-04TB  (hidden comment: CHS_04TB)
S2  VAL2: SW  (hidden comment: SKHMQKE010)
TP9  TP  (value not drawn)
TP10  TP  (value not drawn)
TP11  TP  (value not drawn)
TP12  TP  (value not drawn)
TP13  TP  (value not drawn)
TP14  TP  (value not drawn)
TP15  TP  (value not drawn)
TP16  TP  (value not drawn)
U?#5  DATE: 2023/03/24  REVISION: 01  SHEETNUMBER: 5/10  FUNCTION: CPLD  TITLE: Multi Level Inverter using MOSFET  DRAWINGNUMBER: RD208-SCHEMATIC-01  (hidden comment: WAKU_DEF100)

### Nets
GND_D: C40.2 C41.2 C42.2 C46.2 C102.2 CN4.1 CN4.3 CN4.5 CN4.7 CN4.9 CN4.11 CN4.13 IC7.21(GND) IC7.25(GND) IC7.31(GND) IC7.62(GND) IC7.69(GND) IC7.75(GND) IC7.84(GND) IC7.100(GND) IC22.2(GND) S1.5 S1.6 S1.7 S1.8 S2.3 S2.4 S2.5  [also labelled SIG454, SIG459, SIG466, SIG523, SIG524, SIG525, SIG537, SIG538, SIG539, SIG544]  [project net SIG10]
SIG458: CN4.2 IC7.5(VAUX) IC7.20(VCCIO1) IC7.38(VCCIO1) IC7.51(VCCIO1) IC7.88(VCCIO2) IC7.98(VCCIO2) R74.1 R145.1 R146.1 R147.1 R148.1 R149.1 R150.1 R151.1 R152.1 R153.1  [also labelled SIG460, SIG507, SIG531, SIG549, VP_3R3_PRH_D]  [project net SIG107]
SIG501: C40.1 C41.1 C42.1 IC7.26(VCC) IC7.57(VCC)  [also labelled SIG526, VP_1R8_CPLD_D]
CP_MODE: IC7.7(IO) ; off-sheet CP_MODE
CP_RESET: IC7.8(IO) ; off-sheet CP_RESET
CP_RSV1: IC7.9(IO) ; off-sheet CP_RSV1
CP_RSV2: IC7.10(IO) ; off-sheet CP_RSV2
CP_RSV3: IC7.60(I/O) ; off-sheet CP_RSV3
CP_RSV4: IC7.61(I/O) ; off-sheet CP_RSV4
CP_TCK: IC7.48(TCK) R75.2 ; off-sheet CP_TCK
CP_TDI: IC7.45(TDI) R78.2 ; off-sheet CP_TDI
CP_TDO: IC7.83(TDO) R77.2 ; off-sheet CP_TDO
CP_TMS: IC7.47(TMS) R76.2 ; off-sheet CP_TMS
CP_UH: IC7.30(I/O) ; off-sheet CP_UH
CP_UL: IC7.32(I/O) ; off-sheet CP_UL
CP_VH: IC7.33(I/O) ; off-sheet CP_VH
CP_VL: IC7.34(I/O) ; off-sheet CP_VL
CP_WH: IC7.35(I/O) ; off-sheet CP_WH
CP_WL: IC7.36(I/O) ; off-sheet CP_WL
DBG_LED1: DS1.K(C) IC7.49(I/O) ; off-sheet DBG_LED1
SIG448: DS2.A R146.2
SIG449: DS1.A R145.2
SIG450: DS3.A R147.2
SIG451: DS4.A R148.2
SIG453: DS4.K(C) IC7.53(I/O) ; off-sheet DBG_LED4  [also labelled DBG_LED4]
SIG455: DS3.K(C) IC7.52(I/O) ; off-sheet DBG_LED3  [also labelled DBG_LED3]
SIG456: C102.1 R153.2 R209.1 S2.1 S2.2
SIG457: DS2.K(C) IC7.50(I/O) ; off-sheet DBG_LED2  [also labelled DBG_LED2]
SIG461: IC7.99(IO/GSR) R209.2 ; off-sheet CP_SW  [also labelled CP_SW]
SIG462: IC7.94(I/O) ; off-sheet CP_VGS_W6  [also labelled CP_VGS_W6]
SIG463: IC7.95(I/O) ; off-sheet CP_VGS_W7  [also labelled CP_VGS_W7]
SIG464: IC7.96(I/O) ; off-sheet CP_VGS_W8  [also labelled CP_VGS_W8]
SIG465: IC7.93(I/O) ; off-sheet CP_VGS_W5  [also labelled CP_VGS_W5]
SIG467: IC7.13(IO) TP11.1
SIG468: IC7.11(IO) TP9.1
SIG469: IC7.90(I/O) ; off-sheet CP_VGS_W2  [also labelled CP_VGS_W2]
SIG470: IC7.24(IO/CDRST) TP14.1
SIG471: IC7.23(IO/GCK1) TP13.1
SIG472: IC7.28(IO/DGE) TP16.1
SIG473: IC7.12(IO) TP10.1
SIG474: IC7.92(I/O) ; off-sheet CP_VGS_W4  [also labelled CP_VGS_W4]
SIG475: IC7.91(I/O) ; off-sheet CP_VGS_W3  [also labelled CP_VGS_W3]
SIG476: IC7.27(IO/GCK2) TP15.1
SIG477: IC7.89(I/O) ; off-sheet CP_VGS_W1  [also labelled CP_VGS_W1]
SIG478: IC7.14(IO) TP12.1
SIG479: IC7.66(I/O) ; off-sheet CP_VGS_U2  [also labelled CP_VGS_U2]
SIG480: IC7.65(I/O) ; off-sheet CP_VGS_U1  [also labelled CP_VGS_U1]
SIG481: IC7.73(I/O) ; off-sheet CP_VGS_U8  [also labelled CP_VGS_U8]
SIG485: IC7.82(I/O) ; off-sheet CP_VGS_V7  [also labelled CP_VGS_V7]
SIG487: IC7.85(I/O) ; off-sheet CP_VGS_V8  [also labelled CP_VGS_V8]
SIG492: IC7.22(IO/GCK0) R79.2 ; off-sheet CPLD_CLK  [also labelled CPLD_CLK]
SIG493: IC7.81(I/O) ; off-sheet CP_VGS_V6  [also labelled CP_VGS_V6]
SIG495: IC7.77(I/O) ; off-sheet CP_VGS_V2  [also labelled CP_VGS_V2]
SIG497: IC7.78(I/O) ; off-sheet CP_VGS_V3  [also labelled CP_VGS_V3]
SIG498: IC7.80(I/O) ; off-sheet CP_VGS_V5  [also labelled CP_VGS_V5]
SIG503: IC7.76(I/O) ; off-sheet CP_VGS_V1  [also labelled CP_VGS_V1]
SIG504: IC7.79(I/O) ; off-sheet CP_VGS_V4  [also labelled CP_VGS_V4]
SIG506: IC7.56(I/O) R212.2 ; off-sheet DBG_SW3  [also labelled DBG_SW3]
SIG508: IC7.54(I/O) R210.2 ; off-sheet DBG_SW1  [also labelled DBG_SW1]
SIG509: IC7.70(I/O) ; off-sheet CP_VGS_U5  [also labelled CP_VGS_U5]
SIG511: IC7.55(I/O) R211.2 ; off-sheet DBG_SW2  [also labelled DBG_SW2]
SIG513: IC7.71(I/O) ; off-sheet CP_VGS_U6  [also labelled CP_VGS_U6]
SIG514: IC7.72(I/O) ; off-sheet CP_VGS_U7  [also labelled CP_VGS_U7]
SIG515: IC7.58(I/O) R213.2 ; off-sheet DBG_SW4  [also labelled DBG_SW4]
SIG521: IC7.68(I/O) ; off-sheet CP_VGS_U4  [also labelled CP_VGS_U4]
SIG522: IC7.67(I/O) ; off-sheet CP_VGS_U3  [also labelled CP_VGS_U3]
SIG530: C46.1 IC22.1(ST) IC22.4(VDD) R74.2
SIG532: R152.2 R213.1 S1.4
SIG533: R151.2 R212.1 S1.3
SIG534: R149.2 R210.1 S1.1
SIG535: IC22.3(OUT) R79.1
SIG536: R150.2 R211.1 S1.2
SIG540: CN4.10 R78.1
SIG541: CN4.6 R75.1
SIG542: CN4.4 R76.1
SIG543: CN4.8 R77.1

Not connected (* = marked no-connect by the designer): CN4 12 14; IC7 1(IO/GTS2) 2(IO/GTS3) 3(IO/GTS0) 4(IO/GTS1) 6(IO) 15(IO) 16(IO) 17(IO) 18(IO) 19(IO) 29(I/O) 37(I/O) 39(I/O) 40(I/O) 41(I/O) 42(I/O) 43(I/O) 44(I/O) 46(I/O) 59(I/O) 63(I/O) 64(I/O) 74(I/O) 86(I/O) 87(I/O) 97(I/O)

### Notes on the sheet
- X4

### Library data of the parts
C40 = GRM188R61A106ME69D: MANUFACTURER: MURATA; ITEM: CAP Ceramic; TIME: 08:44:46; UPDATEUSER: t5459927; SAVECOUNT: 1; OriginalSymbolOrigin: (0,0); INSTANCENAME: INS15854292
C41 = GRM155R71E104KE14D: MANUFACTURER: MURATA; ITEM: CAP Ceramic; SIZECODESMD: 1005; TIME: 08:44:45; UPDATEUSER: t5459927; SAVECOUNT: 1; OriginalSymbolOrigin: (0,0); INSTANCENAME: INS15854312
C42 = GRM155R71E104KE14D: MANUFACTURER: MURATA; ITEM: CAP Ceramic; SIZECODESMD: 1005; TIME: 08:44:45; UPDATEUSER: t5459927; SAVECOUNT: 1; OriginalSymbolOrigin: (0,0); INSTANCENAME: INS15854332
C46 = GRM155R71E104KE14D: MANUFACTURER: MURATA; ITEM: CAP Ceramic; SIZECODESMD: 1005; TIME: 08:44:45; UPDATEUSER: t5459927; SAVECOUNT: 1; OriginalSymbolOrigin: (0,0); INSTANCENAME: INS15966208
C102 = GRM188R61A106ME69D: MANUFACTURER: MURATA; ITEM: CAP Ceramic; TIME: 08:44:46; UPDATEUSER: t5459927; SAVECOUNT: 1; OriginalSymbolOrigin: (0,0); INSTANCENAME: INS15982721
CN4 = 0878311420: MANUFACTURER: Molex; ITEM: Connector; TIME: 08:44:46; UPDATEUSER: t5459927; SAVECOUNT: 1; SAVEAREA0: -11456,-20726,18408,1136; OriginalSymbolOrigin: (0,0); INSTANCENAME: INS15810166
DS1 = SMLD12EN1WT86: MANUFACTURER: ROHM; ITEM: LED; VAL2: GREEN; SIZECODESMD: 1608; TIME: 08:44:46; UPDATEUSER: t5459927; SAVECOUNT: 1; OriginalSymbolOrigin: (0,0); INSTANCENAME: INS16374367
DS2 = SMLD12EN1WT86: MANUFACTURER: ROHM; ITEM: LED; VAL2: GREEN; SIZECODESMD: 1608; TIME: 08:44:46; UPDATEUSER: t5459927; SAVECOUNT: 1; OriginalSymbolOrigin: (0,0); INSTANCENAME: INS16374465
DS3 = SMLD12EN1WT86: MANUFACTURER: ROHM; ITEM: LED; VAL2: GREEN; SIZECODESMD: 1608; TIME: 08:44:46; UPDATEUSER: t5459927; SAVECOUNT: 1; OriginalSymbolOrigin: (0,0); INSTANCENAME: INS16374497
DS4 = SMLD12EN1WT86: MANUFACTURER: ROHM; ITEM: LED; VAL2: GREEN; SIZECODESMD: 1608; TIME: 08:44:46; UPDATEUSER: t5459927; SAVECOUNT: 1; OriginalSymbolOrigin: (0,0); INSTANCENAME: INS16374529
IC7 = XC2C256_7VQG100C: MANUFACTURER: Xilinx; ITEM: IC CPLD; TIME: 08:44:46; UPDATEUSER: PS4_common_PC; UPDATETIME: 16:00:18; SAVECOUNT: 3; SAVEAREA0: -110321,-158692,133213,-47724; OriginalSymbolOrigin: (0,0)
IC22 = ASE_20_000MHZ_LC_T: MANUFACTURER: Abracon; ITEM: Crystal  Oscillator; VAL2: 20.0MHz; SIZECODESMD: 3225; VALUE4: 50ppm; TIME: 08:44:46; UPDATEUSER: PS4_common_PC; UPDATETIME: 16:08:33; SAVECOUNT: 3; SAVEAREA0: -31083,-23837,46439,11486; OriginalSymbolOrigin: (0,0)
R74 = ERJ2GE0R00X: MANUFACTURER: Panasonic; ITEM: Register; VAL2: 1/10W; SIZECODESMD: 1005; TIME: 08:44:45; UPDATEUSER: t5459927; SAVECOUNT: 1; OriginalSymbolOrigin: (0,0); INSTANCENAME: INS15966188
R75 = ERJ2RKF22R0X: MANUFACTURER: Panasonic; ITEM: Register; VAL2: 100mW; SIZECODESMD: 1005; TIME: 08:44:46; UPDATEUSER: t5459927; SAVECOUNT: 1; OriginalSymbolOrigin: (0,0); INSTANCENAME: INS15815381
R76 = ERJ2RKF22R0X: MANUFACTURER: Panasonic; ITEM: Register; VAL2: 100mW; SIZECODESMD: 1005; TIME: 08:44:46; UPDATEUSER: t5459927; SAVECOUNT: 1; OriginalSymbolOrigin: (0,0); INSTANCENAME: INS15815301
R77 = ERJ2RKF22R0X: MANUFACTURER: Panasonic; ITEM: Register; VAL2: 100mW; SIZECODESMD: 1005; TIME: 08:44:46; UPDATEUSER: t5459927; SAVECOUNT: 1; OriginalSymbolOrigin: (0,0); INSTANCENAME: INS15815427
R78 = ERJ2RKF22R0X: MANUFACTURER: Panasonic; ITEM: Register; VAL2: 100mW; SIZECODESMD: 1005; TIME: 08:44:46; UPDATEUSER: t5459927; SAVECOUNT: 1; OriginalSymbolOrigin: (0,0); INSTANCENAME: INS15815473
R79 = ERJ2RKF22R0X: MANUFACTURER: Panasonic; ITEM: Register; VAL2: 100mW; SIZECODESMD: 1005; TIME: 08:44:46; UPDATEUSER: t5459927; SAVECOUNT: 1; OriginalSymbolOrigin: (0,0); INSTANCENAME: INS15966292
R145-R148 = ERJ2RKF1001X: MANUFACTURER: Panasonic; ITEM: Register; VAL2: 100mW; SIZECODESMD: 1005; TIME: 08:44:45; UPDATEUSER: t5459927; SAVECOUNT: 1; OriginalSymbolOrigin: (0,0); INSTANCENAME: INS17200488
R149 = ERJ2RKF1002X: MANUFACTURER: Panasonic; ITEM: Register; VAL2: 100mW; SIZECODESMD: 1005; TIME: 08:44:45; UPDATEUSER: t5459927; SAVECOUNT: 1; OriginalSymbolOrigin: (0,0); INSTANCENAME: INS17131726
R150 = ERJ2RKF1002X: MANUFACTURER: Panasonic; ITEM: Register; VAL2: 100mW; SIZECODESMD: 1005; TIME: 08:44:45; UPDATEUSER: t5459927; SAVECOUNT: 1; OriginalSymbolOrigin: (0,0); INSTANCENAME: INS17131576
R151 = ERJ2RKF1002X: MANUFACTURER: Panasonic; ITEM: Register; VAL2: 100mW; SIZECODESMD: 1005; TIME: 08:44:45; UPDATEUSER: t5459927; SAVECOUNT: 1; OriginalSymbolOrigin: (0,0); INSTANCENAME: INS17131426
R152 = ERJ2RKF1002X: MANUFACTURER: Panasonic; ITEM: Register; VAL2: 100mW; SIZECODESMD: 1005; TIME: 08:44:45; UPDATEUSER: t5459927; SAVECOUNT: 1; OriginalSymbolOrigin: (0,0); INSTANCENAME: INS17130644
R153 = ERJ2RKF1002X: MANUFACTURER: Panasonic; ITEM: Register; VAL2: 100mW; SIZECODESMD: 1005; TIME: 08:44:45; UPDATEUSER: t5459927; SAVECOUNT: 1; OriginalSymbolOrigin: (0,0); INSTANCENAME: INS15982142
R209 = ERJ2RKF1000X: MANUFACTURER: Panasonic; ITEM: Register; VAL2: 100mW; SIZECODESMD: 1005; TIME: 08:44:46; UPDATEUSER: t5459927; SAVECOUNT: 1; OriginalSymbolOrigin: (0,0); INSTANCENAME: INS16644148
R210 = ERJ2RKF1000X: MANUFACTURER: Panasonic; ITEM: Register; VAL2: 100mW; SIZECODESMD: 1005; TIME: 08:44:46; UPDATEUSER: t5459927; SAVECOUNT: 1; OriginalSymbolOrigin: (0,0); INSTANCENAME: INS16645400
R211 = ERJ2RKF1000X: MANUFACTURER: Panasonic; ITEM: Register; VAL2: 100mW; SIZECODESMD: 1005; TIME: 08:44:46; UPDATEUSER: t5459927; SAVECOUNT: 1; OriginalSymbolOrigin: (0,0); INSTANCENAME: INS16645432
R212 = ERJ2RKF1000X: MANUFACTURER: Panasonic; ITEM: Register; VAL2: 100mW; SIZECODESMD: 1005; TIME: 08:44:46; UPDATEUSER: t5459927; SAVECOUNT: 1; OriginalSymbolOrigin: (0,0); INSTANCENAME: INS16645464
R213 = ERJ2RKF1000X: MANUFACTURER: Panasonic; ITEM: Register; VAL2: 100mW; SIZECODESMD: 1005; TIME: 08:44:46; UPDATEUSER: t5459927; SAVECOUNT: 1; OriginalSymbolOrigin: (0,0); INSTANCENAME: INS16645496
S1 = CHS_04TB: MANUFACTURER: COPAL; ITEM: DIP Switch 4P; VAL2: 50V 100mA; TIME: 08:44:46; UPDATEUSER: t5459927; SAVECOUNT: 1; SAVEAREA0: -8722,-16798,20771,4793; OriginalSymbolOrigin: (0,0); INSTANCENAME: INS16410549
S2 = SKHMQKE010: MANUFACTURER: ALPS; ITEM: Tactile Switch SMD; TIME: 08:44:46; UPDATEUSER: t5459927; SAVECOUNT: 1; OriginalSymbolOrigin: (0,0); INSTANCENAME: INS16410953
TP9-TP16 = TP: TIME: 16:12:21; UPDATEUSER: fukuda-y; UPDATETIME: 16:18:11; SAVECOUNT: 2; SAVEAREA0: -242,-92,12810,7836; OriginalSymbolOrigin: (0,7620); VAL3: TH Hole dia. 1.0; COMP: TP-TH1.0-L1.6
U?#5 = WAKU_DEF100: PLOTTIME: HH:MM; SAVEAREA0: 185750,-43960,448537,75779; TIME: 14:30:25; UPDATEUSER: PS4_common_PC; UPDATETIME: 08:24:48; SAVECOUNT: 8; OriginalSymbolOrigin: (10160,284480)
